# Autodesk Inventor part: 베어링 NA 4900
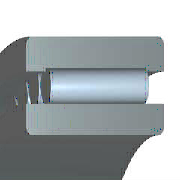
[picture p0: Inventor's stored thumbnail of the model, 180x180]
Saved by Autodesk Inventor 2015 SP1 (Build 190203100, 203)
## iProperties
Created: 2009-02
Part Number: 베어링 NA 4900
Material: Steel, Mild
Description: 니들 롤러 베어링 - 경계 치수 및 공차
Document SubType Name: Modeling
Standard: KS B 2029
Designer: SeoGD™
Standards Organization: KS
Language: ko-KR
Size Designation: NA 4900 - 10 x 22 x 13
Categories: <MemberInstance><Categories><Category DisplayName="샤프트 부품" InternalName="7f7aeb1f-a693-4053-b835-cee3144e0d98" Mnemonic="SHFT"><Category DisplayName="베어링" Inter
Density: 7.86 g/cm^3
Appearance: Metal-Steel
Mass: 23.8213 g
Surface Area: 38.613 cm^2
Volume: 3.0307 cm^3
IsCustomPart: 0
Author: SeoGD™
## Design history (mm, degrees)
sketch "스케치"
  geometry: L1 (1.857, 9)-(11.143, 9); L2 (11.143, 9)-(11.143, 7); L3 (13, 7)-(0, 7); L4 (1.857, 7)-(1.857, 9); L5 (1.857, 8)-(11.143, 8); L6 (6.5, 8)-(6.5, 7); L7 (0, 5)-(13, 5); L8 (0, 11)-(13, 11); L9 (13, 5)-(13, 7); L10 (13, 8.8)-(13, 11); L11 (1.857, 8.8)-(0, 8.8); L12 (11.143, 8.8)-(13, 8.8); L13 (-6, 0)-(36, 0) reference; L14 (0, -1.9)-(0, 14.9) reference
  constraints: 24 end point, 8 point on line, 3 midpoint, 3 parallel, 3 perpendicular, 2 symmetric about line, 1 horizontal, 1 other
  dimensions: "d6" = 10 diameter of L7 L13 (= WD); "d7" = 14 diameter of L3 L13 (= KID1); "d8" = 22 diameter of L8 L13 (= BD); "d9" = 16 diameter of L6.start L13 (= 0.5 x WD + 0.5 x BD); "d10" = 17.6 diameter of L12 L13 (= 0.9 x BD + 0.9 x WD - 0.8 x KID1); "d11" = 18 diameter of L1 L13 (= BD + WD - KID1); "d12" = 1.85714 distance between parallel lines of L14 L4 (= 0.142857 x KB); "d13" = 13 distance between parallel lines of L14 L9 (= KB); "d14" = 11.14286 distance between parallel lines of L14 L2 (= 0.857143 x KB)
revolve "본체" stored, may be unused: angle "d17" = 90 deg
revolve "롤러" stored, may be unused: angle "d18" = 90 deg
pattern_circular "IDS_ARRAYROLLER[SIMPL:T]" dims angle "d2" = 360 deg
body "Solid1"
fillet "모깎기1" dims "d0" = 0.3 (= KRS)
other parameters: "WD" = 10 [user parameter; used in 6 equation terms], "BD" = 22 [user parameter; used in 6 equation terms], "KB" = 13 [user parameter; used in 3 equation terms], "KID1" = 14 [user parameter; used in 4 equation terms], "KRS" = 0.3 [user parameter; used in 1 equation term], "d3" = 0, "d4" = 0, "d5" = 0, "d15" = 0, "d16" = 0, "BC0" = 9150000 [user parameter], "WR" = 5 (= 0.5 x WD) [user parameter], "BBA" = 0 [user parameter], "BC" = 8150000 [user parameter], "BR" = 11 (= 0.5 x BD) [user parameter]
